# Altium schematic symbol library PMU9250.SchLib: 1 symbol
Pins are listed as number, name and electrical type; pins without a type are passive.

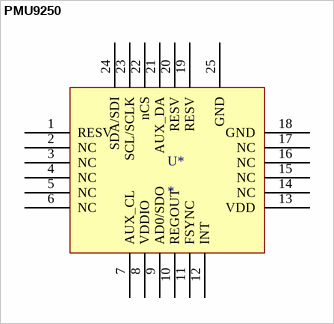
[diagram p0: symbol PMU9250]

## PMU9250
designator U*
pins: 1 RESV, 2 NC, 3 NC, 4 NC, 5 NC, 6 NC, 7 AUX_CL, 8 VDDIO, 9 AD0/SDO, 10 REGOUT, 11 FSYNC, 12 INT, 13 VDD, 14 NC, 15 NC, 16 NC, 17 NC, 18 GND, 19 RESV, 20 RESV, 21 AUX_DA, 22 nCS, 23 SCL/SCLK, 24 SDA/SDI, 25 GND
